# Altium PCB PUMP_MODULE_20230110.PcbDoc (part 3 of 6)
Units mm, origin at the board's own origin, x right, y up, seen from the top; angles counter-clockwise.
Board outline 260.15 x 142.01 mm, 4 copper layers (Top Layer, Mid-Layer 1, Mid-Layer 2, Bottom Layer); 422 components, 240 nets, 1746 pads, 416 vias.
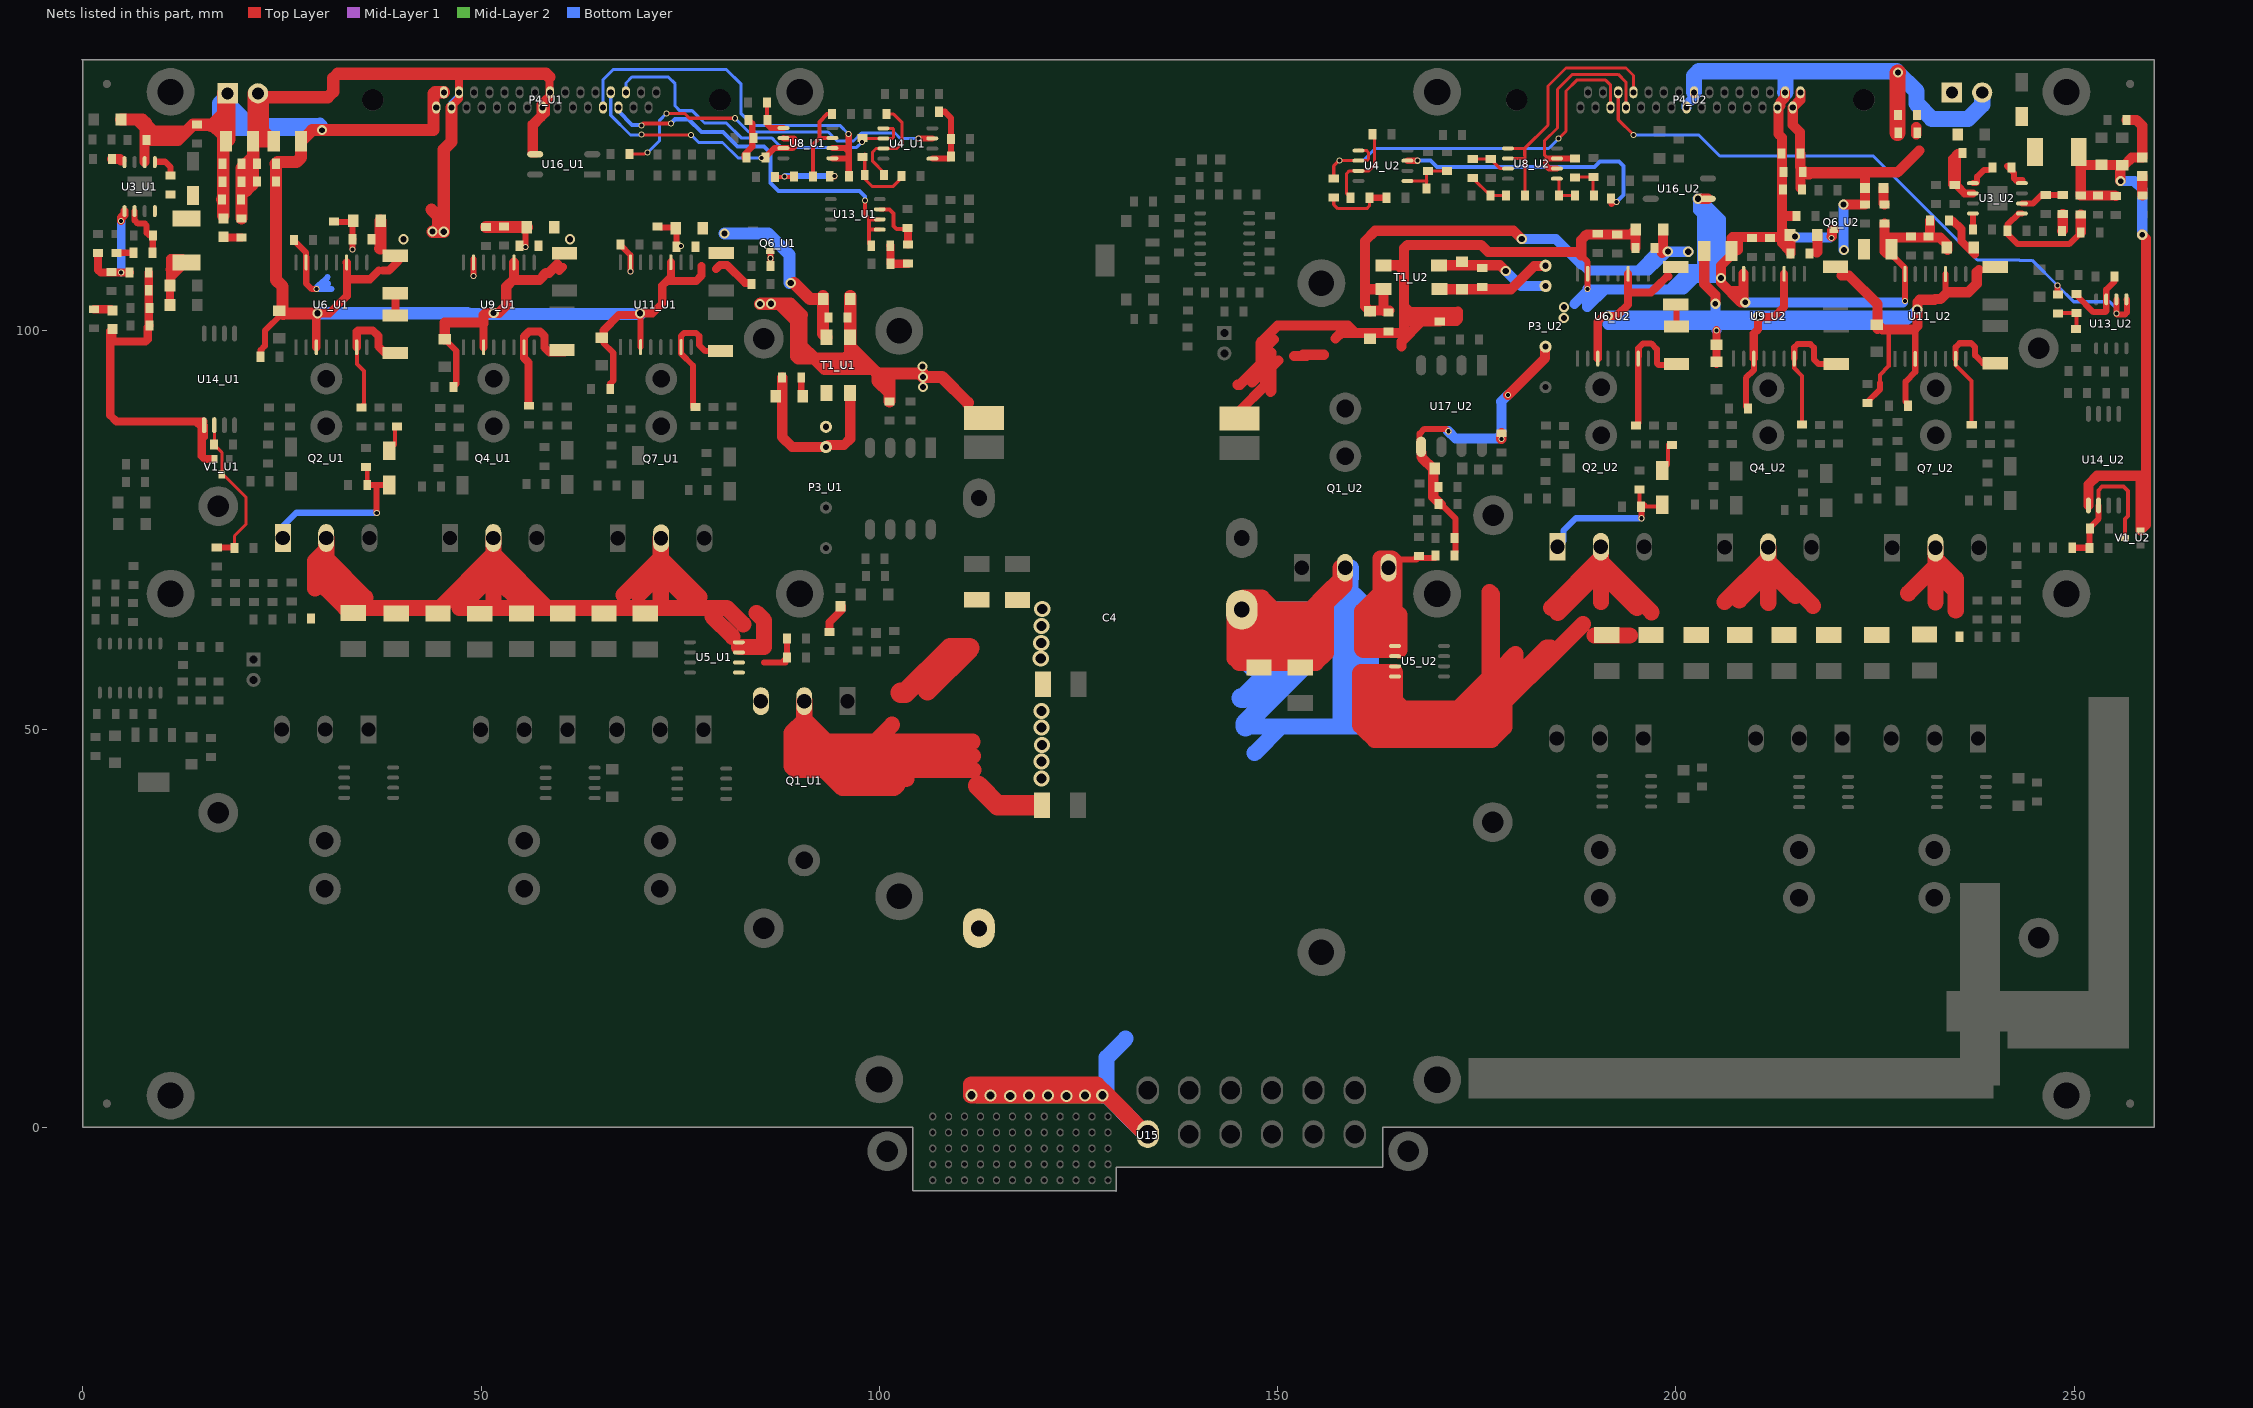
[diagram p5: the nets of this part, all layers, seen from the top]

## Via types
v1: diameter 0.762, hole 0.508, Top Layer to Bottom Layer, 208 vias
v2: diameter 2.032, hole 1.27, Top Layer to Bottom Layer, 78 vias
v3: diameter 1.27, hole 0.762, Top Layer to Bottom Layer, 61 vias
v4: diameter 1.524, hole 1.016, Top Layer to Bottom Layer, 53 vias
v5: diameter 1.27, hole 0.711, Top Layer to Bottom Layer, 16 vias

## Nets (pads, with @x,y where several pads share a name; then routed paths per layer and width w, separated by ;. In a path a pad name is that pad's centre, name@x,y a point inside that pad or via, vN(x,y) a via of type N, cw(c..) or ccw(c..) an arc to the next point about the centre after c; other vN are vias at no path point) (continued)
GND_HVISO_U2: C38_U2.2 C39_U2.2 C40_U2.2 P3_U2.3 R18_U2.2 R34_U2.2 R46_U2.1 U17_U2.5 | length 41.8
  Top Layer w0.762: U17_U2.5@167.818,84.963 167.818,87.097 168.427,87.706 171.12,87.706 v1(171.425,87.401) ; C39_U2.2@170.51,78.181 170.586,78.181 172.339,76.429 R18_U2.2@172.339,72.252
  Top Layer w1.27: U17_U2.5@168.046,84.734 168.046,84.15 169.647,82.55 169.545,82.448 169.545,79.146 C39_U2.2@170.51,78.181 ; v1(178.105,86.436) 178.079,86.462 178.079,86.614 178.105,86.639 R34_U2.2@178.105,87.147 ; v1(178.943,91.948) 183.591,96.596 P3_U2.3@183.591,97.993
  Bottom Layer w1.27: v1(171.425,87.401) 172.339,86.487 177.546,86.487 178.105,87.046 178.105,91.059 178.054,91.11 178.892,91.948 v1(178.943,91.948)
HVCC_IN: C4.1 C17.2 C18.2 C73.2 C74.2 C75.2 C76.2 Q1_U1.2 Q1_U2.2 U15.7 | length 548.8
  Top Layer w2.032: Q1_U1.2@90.572,53.619 Q1_U1.2@90.572,53.518 90.572,51.236 ; 101.6,50.546 99.466,48.412 ; 102.286,43.028 101.854,42.596 95.377,42.596 94.234,43.739 ; 103.378,43.739 94.234,43.739 ; 111.684,48.412 99.466,48.412 ; 111.735,46.634 91.948,46.634 ; 111.785,44.856 93.167,44.856 ; 112.37,4.039 v4(111.557,4.039) v4@111.531,4.013 ; v4@116.713,4.039 119.736,4.039 ; v4@118.745,4.394 118.77,4.394 119.024,4.14 119.837,4.14 ; 121.641,5.41 121.666,5.385 ; v4@123.749,4.039 119.736,4.039 ; 126.797,4.039 v4(127.991,4.039) v4@128.566,4.039 ; v4@128.422,4.14 v4@127.991,4.14 ; U15.7@133.741,-0.837 U15.7@133.7,-0.837 U15.7@133.527,-0.837 ; Q1_U2.2@157.916,70.256 157.916,68.838 156.058,66.98 ; Q1_U2.2@158.475,70.256 158.394,70.176 158.394,68.072 156.058,65.735 ; 88.976,46.812 88.976,49.53 90.572,51.126 ; 88.976,46.812 88.976,45.339 89.459,44.856 90.932,44.856 ; 88.976,46.812 90.932,44.856 ; 90.572,47.68 90.572,47.452 91.948,46.076 ; 90.572,47.68 91.618,46.634 91.948,46.634 ; 90.572,47.68 90.572,49.788 ; 90.572,49.788 90.572,51.126 ; 90.572,49.788 91.948,48.412 ; 90.572,51.126 90.572,51.236 ; 90.572,51.236 93.396,48.412 ; 90.932,44.856 93.116,44.856 ; 91.948,46.076 93.167,44.856 ; 91.948,46.076 91.948,46.634 ; 91.948,46.076 91.948,46.025 93.116,44.856 ; 91.948,46.634 91.948,48.412 ; 91.948,48.412 93.396,48.412 ; 93.116,44.856 94.234,43.739 ; 93.116,44.856 93.167,44.856 ; 93.396,48.412 99.466,48.412 ; v4@111.531,4.013 v4(113.944,4.013) v4(125.806,4.013) 126.619,4.013 v4@126.492,4.14 ; v4@111.531,4.013 111.531,5.385 121.666,5.385 ; 119.736,4.039 119.837,4.14 ; 119.837,4.14 v4@122.911,4.14 ; 121.666,5.385 126.746,5.385 ; 121.666,5.385 v4@122.911,4.14 ; v4@122.911,4.14 v4@126.492,4.14 ; v4@126.492,4.14 v4@127.991,4.14 ; 126.746,5.385 v4@127.991,4.14 ; 126.746,5.385 127.305,5.385 v4@128.651,4.039 ; v4@128.566,4.039 v4@128.651,4.039 ; v4@128.566,4.039 133.442,-0.837 U15.7@133.527,-0.837 ; v4@128.651,4.039 U15.7@133.527,-0.837 ; 144.628,60.96 144.628,58.877 145.186,58.318 154.813,58.318 156.058,59.563 156.058,61.087 ; 144.628,60.96 144.628,64.128 C4.1@145.5,65 ; 144.628,60.96 146.075,59.512 154.28,59.512 154.381,59.411 156.058,61.087 ; C4.1@145.5,63.771 C4.1@145.5,65 ; C4.1@145.5,63.771 145.5,62.399 146.355,61.544 154.635,61.544 156.058,62.967 ; C4.1@145.5,63.771 145.847,63.424 154.864,63.424 156.058,64.618 ; C4.1@145.5,65 149.53,65 ; C4.1@145.5,65 145.5,66.328 145.694,66.523 148.007,66.523 149.53,65 ; 149.53,65 154.078,65 156.058,66.98 ; 156.058,61.087 156.058,62.967 ; 156.058,62.967 156.058,64.618 ; 156.058,64.618 156.058,65.735 ; 156.058,65.735 156.058,66.98
  Top Layer w2.54: 102.692,54.534 102.667,54.559 103.276,54.559 108.89,60.173 111.328,60.173 106.045,54.889 ; 112.395,42.901 114.833,40.462 C76.2@119.913,40.462
  Mid-Layer 1 w2.032: v4@121.717,4.166 121.742,4.14 128.464,4.14 130.461,2.143 130.461,2.127 133.425,-0.837 U15.7@133.7,-0.837 U15.7@133.741,-0.837
  Mid-Layer 2 w2.032: v4@111.76,4.699 125.628,4.699 126.187,4.14 v4@127.94,4.14 ; v4@111.912,4.496 112.37,4.039 v4(127.991,4.039) 128.566,4.039 130.461,2.143 130.461,2.101 133.4,-0.837 U15.7@133.7,-0.837 U15.7@133.741,-0.837 ; 112.09,5.334 126.746,5.334 v4@127.94,4.14 ; v4@128.422,4.14 v4@127.94,4.14
  Bottom Layer w2.032: v4(127.991,4.039) v4@128.525,4.039 ; 130.912,11.151 128.525,8.764 v4@128.525,4.039 ; U15.7@133.7,-0.837 133.4,-0.837 v4@128.525,4.039 ; 145.974,50.343 150.47,50.343 ; 147.117,46.99 150.47,50.343 ; 147.701,61.468 153.34,61.468 154.991,61.468 157.916,64.393 ; 147.777,59.817 147.777,59.842 151.714,59.842 155.092,59.842 155.575,59.842 157.916,62.184 ; 158.043,68.449 Q1_U2.2@158.043,70.256 ; Q1_U2.2@159.182,70.256 159.182,68.991 159.156,69.016 159.156,67.335 159.842,66.65 ; 150.47,50.343 157.302,50.343 ; 157.302,50.343 158.75,50.343 ; 157.302,50.343 157.916,50.957 157.916,62.184 ; 157.916,62.184 157.916,64.393 ; 157.916,64.393 157.916,66.984 ; 157.916,66.984 157.916,68.102 154.814,65 C4.1@145.5,65 147.203,63.297 154.229,63.297 157.916,66.984 ; 158.75,50.343 161.138,50.343 161.722,50.927 161.722,64.77 159.842,66.65 ; 158.75,50.343 159.842,51.435 159.842,66.65
  Bottom Layer w2.54: 145.466,53.899 145.771,53.899 149.835,57.963 ; 145.974,50.343 145.974,50.724 155.092,59.842 ; 146.812,57.963 149.835,57.963 ; 153.34,61.468 151.714,59.842 149.835,57.963
  other v2: 120.345,43.815 120.345,45.923 120.421,48.006 120.371,50.19 120.371,52.299 120.269,58.852 120.32,60.808 120.345,62.967 120.447,65.1
  other v4: 116.434,3.962 123.495,3.962 118.796,3.988 121.158,3.988
HVCC_U1: C15_U1.2 C16_U1.2 C20_U1.2 C70_U1.2 C71_U1.2 C72_U1.2 C77_U1.2 C78_U1.2 Q2_U1.2 Q4_U1.2 Q7_U1.2 R74_U1.2 U5_U1.3 U5_U1.4 | length 159.1
  Top Layer w2.032: Q2_U1.2@30.56,74 Q2_U1.2@30.56,72.517 ; 33.604,66.497 30.56,69.541 ; 35.484,66.497 30.56,71.421 ; Q4_U1.2@51.56,74 51.56,71.935 ; 67.894,66.853 72.56,71.519 ; 69.774,66.878 72.56,69.664 ; Q7_U1.2@72.56,74 72.56,71.519 ; 76.048,66.269 72.56,69.756 ; 77.419,66.573 72.56,71.433 ; 79.045,64.135 81.585,61.595 ; 82.423,60.3 85.522,60.3 85.522,63.652 84.582,64.592 ; 82.906,63.17 80.848,65.227 72.644,65.227 ; 30.56,69.041 30.56,69.541 ; 30.56,69.041 30.56,67.611 32.944,65.227 44.856,65.227 51.56,71.931 ; 30.56,69.041 29.159,67.64 29.159,71.116 Q2_U1.2@30.56,72.517 ; 30.56,69.541 30.56,71.421 ; 30.56,71.421 Q2_U1.2@30.56,72.517 ; 51.56,69.344 51.56,65.483 51.816,65.227 ; 51.56,69.344 C72_U1.2@55.677,65.227 ; 51.56,69.344 51.56,69.492 ; 51.56,69.492 51.56,71.931 ; 51.56,69.492 47.295,65.227 51.816,65.227 ; 51.56,71.931 51.56,71.935 ; 51.56,71.935 58.268,65.227 ; 51.816,65.227 C72_U1.2@55.677,65.227 ; C72_U1.2@55.677,65.227 58.268,65.227 ; 58.268,65.227 72.644,65.227 ; 72.56,69.664 72.56,69.756 ; 72.56,69.664 72.56,65.311 72.644,65.227 ; 72.56,69.756 72.56,71.433 ; 72.56,71.433 72.56,71.519
HVCC_U2: C15_U2.2 C16_U2.2 C20_U2.2 C70_U2.2 C71_U2.2 C72_U2.2 C77_U2.2 C78_U2.2 Q2_U2.2 Q4_U2.2 Q7_U2.2 R74_U2.2 U5_U2.3 U5_U2.4 | length 255.8
  Top Layer w2.032: 172.822,52.73 175.514,55.423 ; 174.142,52.73 175.514,54.102 175.514,55.423 ; 174.6,51.054 176.581,53.035 ; 176.047,52.553 165.76,52.553 164.744,53.569 U5_U2.4@164.744,56.617 164.744,57.15 163.271,57.15 ; 176.505,50.876 178.283,52.654 ; 183.248,58.102 188.341,63.195 ; 184.252,60.249 183.794,60.249 179.857,56.312 ; 184.353,65.253 Q2_U2.2@190.601,71.501 ; 184.506,59.411 178.46,53.365 178.46,50.241 176.886,48.666 174.295,48.666 ; 185.166,64.567 190.601,70.002 ; C16_U2.2@189.763,61.747 194.208,61.747 ; 190.601,65.964 190.601,69.723 ; Q2_U2.2@190.601,72.83 Q2_U2.2@190.601,71.501 ; 195.123,65.202 190.601,69.723 ; 196.952,64.668 190.601,71.019 ; 206.096,65.964 Q4_U2.2@211.601,71.47 ; 207.95,66.167 211.601,69.819 ; Q4_U2.2@211.601,72.83 Q4_U2.2@211.601,71.47 ; 211.633,65.862 211.601,65.894 211.601,69.819 ; 215.011,66.7 211.601,70.11 ; 217.221,65.481 Q4_U2.2@211.601,71.101 ; 229.184,67.031 229.159,67.056 232.601,70.499 ; 232.588,65.938 232.601,65.952 232.601,69.862 ; Q7_U2.2@232.601,72.83 Q7_U2.2@232.601,71.411 ; 235.052,67.412 232.601,69.862 ; 235.128,64.897 235.128,68.885 Q7_U2.2@232.601,71.411 ; 161.036,49.809 162.179,48.666 164.694,48.666 ; 161.036,49.809 163.551,49.809 ; 161.036,49.809 160.35,50.495 160.35,57.023 160.477,57.15 161.747,57.15 ; 161.747,57.15 161.417,56.82 161.417,51.943 163.551,49.809 ; 161.747,57.15 163.271,57.15 ; 163.271,57.15 163.271,52.248 164.871,50.648 176.276,50.648 174.295,48.666 ; 163.551,49.809 164.694,48.666 ; 164.694,48.666 174.295,48.666 ; 175.514,55.423 176.581,56.49 ; 176.581,53.035 176.581,56.49 ; 176.581,53.035 178.079,54.534 ; 176.581,56.49 176.911,56.82 176.911,66.904 176.581,67.234 176.581,56.49 ; 178.079,54.534 179.857,56.312 ; 178.079,54.534 178.079,57.658 179.857,59.436 179.857,56.312 ; 190.601,69.723 190.601,70.002 ; 190.601,70.002 190.601,71.019 ; 190.601,71.019 Q2_U2.2@190.601,71.501 ; 211.601,69.819 211.601,70.11 ; 211.601,70.11 Q4_U2.2@211.601,71.101 ; Q4_U2.2@211.601,71.101 Q4_U2.2@211.601,71.47 ; 232.601,69.862 232.601,70.499 ; 232.601,70.499 Q7_U2.2@232.601,71.411
HVCCIN_U1: Q1_U1.3 R15_U1.1 R18_U1.1 U5_U1.1 U5_U1.2 | length 6
  Top Layer w0.762: 85.547,58.344 87.757,58.344 ; 88.189,58.344 87.757,58.344 ; R18_U1.1@88.417,61.392 R15_U1.1@88.417,59.004 87.757,58.344
HVCCIN_U2: Q1_U2.3 R15_U2.1 R18_U2.1 U5_U2.1 U5_U2.2 | length 66.2
  Top Layer w0.762: Q1_U2.3@163.356,70.256 164.423,71.323 R15_U2.1@167.411,71.323 ; R15_U2.1@167.361,71.526 167.386,71.501 R18_U2.1@169.774,71.501
  Top Layer w2.032: Q1_U2.3@163.297,69.901 163.297,67.462 162.916,67.081 ; Q1_U2.3@163.356,70.256 163.356,66.26 ; Q1_U2.3@163.483,70.256 Q1_U2.3@163.944,69.795 ; 161.722,59.969 160.757,59.969 160.63,60.096 160.63,64.795 162.916,67.081 ; 161.722,59.969 163.525,59.969 ; 161.722,59.969 161.671,60.02 161.671,64.592 163.347,66.269 ; 162.916,67.081 162.916,71.425 164.321,71.425 164.423,71.323 164.643,71.103 Q1_U2.3@164.643,69.097 ; 162.916,67.081 162.916,66.7 163.347,66.269 ; 163.347,66.269 163.347,60.147 163.525,59.969 ; 163.347,66.269 163.356,66.26 ; 163.356,66.26 163.944,65.672 ; 163.525,59.969 165.151,59.969 165.227,59.893 165.261,59.927 165.261,64.355 164.643,64.973 ; 163.944,65.672 164.643,64.973 ; 163.944,65.672 Q1_U2.3@163.944,69.795 ; Q1_U2.3@163.944,69.795 Q1_U2.3@164.643,69.097 ; 164.643,64.973 Q1_U2.3@164.643,69.097
II_1_AC1_U1: C45_U1.2 P4_U1.12 U8_U1.1 U8_U1.2 | length 50
  Top Layer w0.762: U8_U1.1@94.107,121.666 96.164,121.666 ; U8_U1.2@94.107,122.936 95.733,122.936 96.164,122.504 ; v1(96.139,124.714) 96.164,124.689 96.164,122.504 ; C45_U1.2@96.164,119.405 96.164,121.666 ; 96.164,121.666 96.164,122.504
  Bottom Layer w0.381: P4_U1.12@65.329,128.047 65.329,131.546 66.573,132.791 80.823,132.791 82.652,130.962 82.652,127.254 84.099,125.806 95.047,125.806 v1(96.139,124.714)
II_1_AC1_U2: C45_U2.2 P4_U2.12 U8_U2.1 U8_U2.2 | length 33.3
  Top Layer w0.381: U8_U2.2@178.918,121.641 181.026,121.641 ; U8_U2.1@178.918,122.911 181.026,122.911 ; C45_U2.2@181.077,116.992 181.077,121.996 181.026,122.047 181.026,122.911 ; P4_U2.12@194.668,129.952 194.668,132.052 193.726,132.994 186.207,132.994 183.947,130.734 183.947,125.832 181.026,122.911
II_1_AC2_U1: C48_U1.2 P4_U1.27 U8_U1.6 U8_U1.7 | length 31
  Top Layer w0.381: v1(70.155,124.663) 70.206,124.612 73.558,124.612 ; 73.584,124.587 73.558,124.612 ; v1@76.352,124.562 76.302,124.612 73.558,124.612
  Top Layer w0.762: C48_U1.2@85.471,121.691 85.573,121.691 86.817,122.936 U8_U1.7@87.96,122.936 89.103,122.936 89.332,123.165 89.332,124.054 89.306,124.079 89.306,124.155 88.011,124.155 U8_U1.6@87.96,124.206
  Bottom Layer w0.381: P4_U1.27@66.281,129.952 66.282,127.063 68.758,124.587 v1@70.155,124.587 ; v1(76.352,124.612) 77.318,123.647 80.315,123.647 82.271,121.691 v1(85.192,121.691)
II_1_AC2_U2: C48_U2.2 P4_U2.27 U8_U2.6 U8_U2.7 | length 28.4
  Top Layer w0.381: 183.972,121.641 183.947,121.641 183.49,122.098 183.49,123.825 185.141,125.476 185.141,130.327 187.02,132.207 192.761,132.207 193.716,131.252 P4_U2.27@193.716,128.047
  Top Layer w0.762: U8_U2.6@185.064,120.371 184.099,120.371 183.718,120.752 183.718,121.387 183.972,121.641 U8_U2.7@185.064,121.641 187.3,121.641 C48_U2.2@187.325,121.666
II_1_AC3_U1: C61_U1.2 P4_U1.13 U13_U1.1 U13_U1.2 | length 48.1
  Top Layer w0.508: v1(70.155,125.806) 70.383,126.035 73.838,126.035 v1(73.838,126.06) ; v1(98.222,116.357) 98.222,114.605 98.831,113.995 ; C61_U1.2@98.984,110.693 98.679,110.998 98.679,112.7 ; U13_U1.1@100.051,112.725 98.704,112.725 98.679,112.7 ; U13_U1.2@100.051,113.995 98.831,113.995 ; 98.679,112.7 98.679,113.843 98.831,113.995
  Bottom Layer w0.508: P4_U1.13@67.234,128.047 67.234,127.584 68.961,125.857 70.104,125.857 v1@70.206,125.755 ; v1@73.838,126.035 74.371,126.568 76.048,126.568 77.673,124.943 80.391,124.943 82.182,123.152 85.534,123.152 86.335,122.352 86.335,118.593 87.351,117.577 97.536,117.577 98.222,116.891 v1(98.222,116.357)
II_1_AC3_U2: C61_U2.2 P4_U2.13 U13_U2.1 U13_U2.2 | length 82.6
  Top Layer w0.381: P4_U2.13@192.763,129.952 192.763,126.515 v1(194.691,124.587) v1@194.615,124.663
  Top Layer w0.762: v1(247.904,105.689) 247.904,104.597 C61_U2.2@247.955,104.546 ; U13_U2.2@255.295,103.962 v1(255.295,102.184) 255.397,102.083 256.388,102.083 256.616,102.311 256.616,103.911 U13_U2.1@256.565,103.962
  Bottom Layer w0.381: v1(194.691,124.587) 202.87,124.587 205.511,121.945 ; 205.537,121.945 224.79,121.945 237.846,108.89 243.129,108.89 243.154,108.864 244.729,108.864 v1(247.904,105.689) 249.936,103.657 254.457,103.657 255.295,102.819 v1(255.295,102.184)
  Bottom Layer w0.762: v1@247.879,105.664 v1(247.904,105.689)
II_1_DC1_U1: C31_U1.2 P4_U1.28 U4_U1.1 U4_U1.2 | length 42.7
  Top Layer w0.381: C31_U1.2@98.222,124.155 U4_U1.2@100.508,124.155 101.625,124.155 101.778,124.308 101.778,125.349 101.702,125.425 U4_U1.1@100.508,125.425
  Bottom Layer w0.381: P4_U1.28@68.186,129.952 68.186,131.127 68.936,131.877 73.508,131.877 74.371,131.013 74.371,128.27 74.346,128.245 74.955,127.635 76.505,127.635 78.054,126.086 80.797,126.086 82.652,124.231 86.487,124.231 87.02,123.698 87.681,123.038 97.155,123.038 v1(97.815,123.698)
II_1_DC1_U2: C31_U2.2 P4_U2.28 U4_U2.1 U4_U2.2 | length 52.9
  Top Layer w0.381: C31_U2.2@157.048,119.126 157.048,120.726 157.683,121.361 U4_U2.2@160.147,121.361 160.172,121.387 161.239,121.387 161.417,121.564 161.417,122.403 161.188,122.631 U4_U2.1@160.147,122.631 U4_U2.1@160.223,122.707 ; v1(185.268,124.13) 186.207,125.07 186.207,125.832 ; 186.182,125.806 186.207,125.832 ; P4_U2.28@191.811,128.047 191.811,130.846 191.186,131.47 187.554,131.47 186.207,130.124 186.207,125.832
  Bottom Layer w0.381: v1(157.785,121.387) 160.757,121.387 162.255,122.885 184.023,122.885 v1(185.268,124.13)
II_FLT_U1: R86_U1.1 U4_U1.7 | length 43.6
  Top Layer w0.381: R86_U1.1@68.656,122.199 70.51,122.199 v1@70.752,122.441 ; v1(73.279,127.305) 75.54,127.305 76.149,126.695 v1(81.89,126.695)
  Top Layer w0.762: v1(104.902,124.155) U4_U1.7@106.655,124.155
  Bottom Layer w0.381: v1(70.891,122.377) 72.415,123.901 72.415,126.441 v1(73.279,127.305) ; v1(81.89,126.695) 83.617,124.968 93.574,124.968 94.691,123.85 96.749,123.85 97.739,124.841 101.168,124.841 101.956,124.841 102.641,124.155 v1(104.902,124.155)
II_FLT_U2: R86_U2.1 U4_U2.7 | length 33.6
  Top Layer w0.762: U4_U2.7@166.294,121.361 v1(167.538,121.361) ; 191.922,115.926 192.176,116.18 v1(192.557,116.18)
  Bottom Layer w0.508: v1(167.538,121.361) 169.215,121.361 170.002,120.574 189.763,120.574 190.449,121.26 192.862,121.26 193.421,120.701 193.421,117.043 v1(192.557,116.18)
ISO_+5V_U1: C21_U1.1 C22_U1.1 C23_U1.1 C29_U1.2 C30_U1.2 D3_U1.1 L1_U1.1 R20_U1.2 U14_U1.1 V1_U1.2 | length 56.4
  Top Layer w1.016: C23_U1.1@8.28,107.315 R20_U1.2@8.28,105.105 8.28,100.787 C30_U1.2@8.382,100.686 8.153,100.457 8.153,98.933 7.899,98.679 3.912,98.679 3.708,98.882 D3_U1.1@3.708,100.228 3.454,99.974 3.454,89.408 4.242,88.621 14.224,88.621 ; 10.922,107.721 10.947,107.696 ; C22_U1.1@10.947,103.251 C21_U1.1@10.947,105.715 10.947,106.68 ; U14_U1.1@15.164,88.621 14.224,88.621 ; U14_U1.1@15.189,88.113 15.189,86.665 14.935,86.411 ; V1_U1.2@16.281,83.896 15.342,83.896 14.935,84.303 14.935,86.411 ; 10.947,106.68 10.947,107.696 ; 10.947,106.68 11.074,106.68 L1_U1.1@13.005,108.61 12.497,109.118 10.998,109.118 10.947,109.068 10.947,107.696 ; 14.224,88.621 14.935,87.909 14.935,86.411
ISO_+5V_U2: C21_U2.1 C22_U2.1 C23_U2.1 C29_U2.2 C30_U2.2 D3_U2.1 L1_U2.1 R20_U2.2 U14_U2.1 V1_U2.2 | length 94
  Top Layer w0.508: 253.34,81.509 257.785,81.509
  Top Layer w1.27: L1_U2.1@250.571,122.479 250.571,121.361 L1_U2.1@250.825,121.107 ; U14_U2.1@251.79,78.08 251.79,80.721 252.882,81.813 258.318,81.813 V1_U2.2@258.318,74.955 259.007,75.644 259.007,111.605 v5(258.547,112.065) ; C29_U2.2@255.219,116.942 255.143,117.018 C23_U2.1@250.825,117.018 L1_U2.1@250.825,121.107 ; v5(255.829,118.796) 255.778,118.847 255.778,120.548 C22_U2.1@256.032,120.802 ; C30_U2.2@256.565,126.492 257.81,126.492 258.547,125.755 D3_U2.1@258.547,121.742 257.226,121.742 256.311,120.828 C21_U2.1@253.416,120.828 251.104,120.828 L1_U2.1@250.825,121.107
  Bottom Layer w1.27: v5(255.829,118.796) 257.556,118.796 258.547,117.805 v5(258.547,112.065)
ISO_+15V_U1: C5_U1.1 C6_U1.1 C7_U1.2 C8_U1.2 C9_U1.2 C10_U1.2 C11_U1.2 C19_U1.1 C24_U1.1 C25_U1.2 C34_U1.1 C35_U1.1 C41_U1.1 C42_U1.1 C43_U1.1 C44_U1.1 C49_U1.1 C50_U1.1 C51_U1.1 C52_U1.1 C66_U1.1 C67_U1.1 C68_U1.1 D1_U1.1 D6_U1.1 D11_U1.1 D16_U1.1 P2_U1.1 P4_U1.1 P4_U1.16 R17_U1.1 R51_U1.2 T1_U1.2 U3_U1.2 U6_U1.3 U6_U1.11 U9_U1.3 U9_U1.11 U11_U1.3 U11_U1.11 | length 314.3
  Top Layer w0.762: C68_U1.1@22.327,96.749 22.327,97.587 22.86,98.12 22.86,100.025 25.019,102.184 C43_U1.1@25.095,102.184 ; C51_U1.1@45.441,98.933 46.888,97.485 46.888,93.32 C44_U1.1@46.533,92.964 ; C19_U1.1@65.354,99.162 65.354,98.476 66.599,97.231 66.599,93.751 66.218,93.37 C52_U1.1@66.218,92.71 ; v3@70.002,101.981 70.002,102.006 70.028,101.981 U11_U1.3@70.028,97.968
  Top Layer w1.016: 24.181,106.324 24.257,106.401 ; U6_U1.3@29.312,97.942 29.312,102.057 29.439,102.184 v3(29.464,102.21) 30.988,102.21 33.147,104.369 33.147,108.567 U6_U1.11@33.122,108.592 ; 33.241,106.477 36.068,106.477 37.16,107.569 ; 37.668,107.594 38.456,107.594 D6_U1.1@39.624,108.763 ; U9_U1.3@50.317,97.942 50.317,100.94 ; 59.817,107.518 60.3,108.001 ; C19_U1.1@65.227,98.882 C19_U1.1@65.253,98.908 ; C19_U1.1@65.354,99.162 65.354,100.051 67.285,101.981 70.002,101.981 v3@70.028,101.981 ; v3(69.952,102.21) 71.526,102.21 72.746,103.429 72.746,105.689 73.33,106.274 ; U11_U1.11@73.838,108.618 73.838,106.782 73.33,106.274 ; 77.673,108.128 77.673,106.934 77.013,106.274 73.33,106.274 ; 79.502,107.772 80.01,108.28 80.874,108.28 83.16,105.994 R51_U1.2@83.541,105.994
  Top Layer w1.27: 6.68,126.517 7.772,125.425 U3_U1.2@7.772,121.183 ; C51_U1.1@45.441,98.933 45.441,101.016 45.491,101.067 50.19,101.067 50.317,100.94 50.317,101.956 50.597,102.235 v3(51.587,102.235) 52.222,102.235 53.162,103.175 53.162,105.537 54.127,106.502 U9_U1.11@54.127,108.592 ; 54.407,106.375 57.328,106.375 57.785,106.832 57.785,106.909 58.166,107.29 58.522,107.29 59.563,108.331
  Top Layer w1.524: C24_U1.1@4.801,126.517 6.68,126.517 7.518,126.517 8.001,126.035 8.001,125.882 8.839,125.044 ; 8.001,125.73 8.001,125.298 ; 16.078,125.73 16.231,125.882 ; C10_U1.2@17.501,116.484 C10_U1.2@17.628,116.611 ; D1_U1.1@17.628,114.452 C10_U1.2@17.628,116.611 ; P2_U1.1@17.628,129.845 17.628,127.279 ; C43_U1.1@25.07,102.641 25.07,105.588 24.257,106.401 C8_U1.2@24.257,118.77 24.257,120.955 C9_U1.2@24.232,120.98 24.46,121.209 26.848,121.209 27.407,121.768 C5_U1.1@27.407,123.8 28.804,125.197 v5(30.023,125.197) 44.044,125.197 44.044,129.794 44.202,129.952 P4_U1.16@45.326,129.952 ; C43_U1.1@25.095,102.184 C43_U1.1@25.171,102.108 ; C43_U1.1@25.375,102.184 v3@29.439,102.184 ; 37.338,110.363 37.389,110.414 C49_U1.1@37.389,113.817 ; v3@89.281,106.02 91.288,104.013 C34_U1.1@92.913,104.013 ; C34_U1.1@92.913,104.394 C34_U1.1@92.913,104.013 ; C34_U1.1@92.939,104.013 C34_U1.1@92.913,104.013 ; T1_U1.2@93.345,99.202 92.913,99.634 C34_U1.1@92.913,104.013 ; 8.001,125.298 R17_U1.1@8.001,123.977 9.855,123.977 ; 8.001,125.298 8.255,125.044 8.839,125.044 ; 8.839,125.044 9.881,124.003 9.855,123.977 ; 8.839,125.044 13.005,125.044 ; 9.855,123.977 11.938,123.977 13.005,125.044 ; 13.005,125.044 13.843,125.882 C25_U1.2@14.351,125.882 16.231,125.882 ; 16.231,125.882 C6_U1.1@17.628,124.485 ; 16.231,125.882 17.628,125.882 ; 16.231,125.882 17.628,127.279 ; C10_U1.2@17.628,116.611 C6_U1.1@17.628,124.485 ; C6_U1.1@17.628,124.485 17.628,125.882 ; C6_U1.1@17.628,124.485 17.958,124.155 C6_U1.1@17.958,123.8 18.212,123.8 18.44,124.028 18.44,129.565 P2_U1.1@18.186,129.819 18.186,127.838 17.628,127.279 ; 17.628,125.882 17.628,127.279
  Bottom Layer w1.524: 21.895,125.197 21.869,125.197 ; v3@29.743,102.21 48.285,102.21 48.362,102.133 v3@70.002,102.133 ; v3(80.569,112.217) 86.055,112.217 88.722,109.55 v3@88.722,106.045 ; 18.186,125.908 16.967,127.127 16.967,128.6 P2_U1.1@18.186,129.819 P2_U1.1@18.186,128.88 ; 18.186,125.908 18.186,127.686 ; 18.186,125.908 18.898,125.197 21.869,125.197 ; 18.186,127.686 P2_U1.1@18.186,128.88 ; 18.186,127.686 19.888,125.984 21.082,125.984 ; P2_U1.1@18.186,128.88 21.082,125.984 ; 21.082,125.984 29.743,125.984 29.769,126.009 30.023,125.755 v5(30.023,125.197) 21.869,125.197 ; 21.082,125.984 21.869,125.197
  other v3: 88.875,105.994 40.284,111.506 61.189,111.506
ISO_+15V_U2: C5_U2.1 C6_U2.1 C7_U2.2 C8_U2.2 C9_U2.2 C10_U2.2 C11_U2.2 C19_U2.1 C24_U2.1 C25_U2.2 C34_U2.1 C35_U2.1 C41_U2.1 C42_U2.1 C43_U2.1 C44_U2.1 C49_U2.1 C50_U2.1 C51_U2.1 C52_U2.1 C66_U2.1 C67_U2.1 C68_U2.1 D1_U2.1 D6_U2.1 D11_U2.1 D16_U2.1 P2_U2.1 P4_U2.1 P4_U2.16 R17_U2.1 R51_U2.2 T1_U2.2 U3_U2.2 U6_U2.3 U6_U2.11 U9_U2.3 U9_U2.11 U11_U2.3 U11_U2.11 | length 325.2
  Top Layer w0.508: 225.628,93.421 225.628,94.488 226.72,95.58 226.72,100.051 226.822,100.152
  Top Layer w0.762: C43_U2.1@205.08,96.672 C43_U2.1@205.207,96.545 ; C44_U2.1@209.067,90.246 208.788,90.526 208.788,94.093 209.779,95.083 U9_U2.3@209.779,96.469 ; U9_U2.3@209.702,96.545 U9_U2.3@209.779,96.469 ; U9_U2.3@209.779,96.52 U9_U2.3@209.779,96.469 ; C68_U2.1@224.053,90.932 224.053,91.097 225.628,92.672 225.628,93.421 ; C52_U2.1@229.032,90.907 228.829,91.11 228.829,93.624 230.048,94.844 U11_U2.3@230.048,96.495 230.048,99.974 229.87,100.152 ; U11_U2.11@233.858,107.145 233.858,105.08 234.086,104.851
  Top Layer w1.016: U6_U2.3@190.195,96.52 190.195,101.143 190.906,101.854 v3(191.44,101.854) 192.557,101.854 193.319,102.616 193.345,102.616 194.005,103.276 194.005,104.8 ; U6_U2.11@194.005,107.17 194.005,104.8 ; 199.06,106.858 198.907,106.858 197.561,105.512 196.85,104.8 194.005,104.8 ; C43_U2.1@205.08,95.834 205.08,96.672 C51_U2.1@205.08,98.273 v1(205.08,100.076) ; U9_U2.3@209.779,96.52 209.779,99.67 210.287,100.178 210.287,101.295 210.744,101.752 212.344,101.752 213.589,102.997 U9_U2.11@213.589,107.17 ; C50_U2.1@234.29,113.868 234.747,113.868 235.839,112.776 235.839,111.252 237.515,109.576 ; R17_U2.1@235.331,118.186 236.245,117.272 U3_U2.2@237.287,117.272 ; 235.356,122.326 235.28,122.25 ; 235.28,122.25 235.28,118.618 R17_U2.1@235.001,118.339 234.721,118.339 234.696,118.364 234.696,121.666 235.28,122.25
  Top Layer w1.27: C35_U2.1@164.008,102.54 C35_U2.1@163.307,102.54 ; v3(180.645,111.531) 179.603,112.573 162.255,112.573 160.96,111.277 160.96,105.689 ; 198.247,109.753 198.399,109.906 C41_U2.1@198.399,112.725 ; C6_U2.1@203.556,109.449 203.556,105.893 204.953,104.496 v5@204.953,103.632 ; C8_U2.2@215.621,117.958 C11_U2.2@215.621,120.523 ; C7_U2.2@215.621,122.276 C11_U2.2@215.621,120.523 ; P4_U2.1@215.623,129.952 215.623,128.999 P4_U2.16@214.671,128.047 214.671,125.841 215.57,124.943 215.57,120.574 C11_U2.2@215.621,120.523 ; 217.678,109.855 217.754,109.931 C66_U2.1@217.754,112.039 ; 220.802,106.934 221.742,106.934 225.323,103.353 C19_U2.1@225.323,100.787 ; v3@221.056,115.875 221.082,115.849 R51_U2.2@223.749,115.849 D1_U2.1@223.749,117.958 223.749,119.761 ; C19_U2.1@225.323,100.228 C19_U2.1@225.323,100.787 ; C10_U2.2@230.175,124.638 230.175,125.603 ; 230.556,122.631 227.838,119.913 223.901,119.913 ; 238.049,107.645 237.769,107.366 237.769,105.918 236.703,104.851 234.086,104.851 233.223,103.988 232.512,103.988 232.435,103.911 230.607,103.911 230.327,103.632 230.327,100.609 229.87,100.152 226.822,100.152 225.958,100.152 C19_U2.1@225.323,100.787 ; 160.96,105.689 160.96,103.099 C34_U2.1@161.62,102.438 161.722,102.54 163.246,102.54 ; 160.96,105.689 161.417,105.232 T1_U2.2@163.307,105.232 C35_U2.1@163.307,102.54 ; 163.246,102.54 C35_U2.1@163.307,102.54 ; 163.246,102.54 163.307,102.479 C35_U2.1@163.307,102.54 ; C11_U2.2@215.621,120.523 C11_U2.2@216.23,119.913 ; C11_U2.2@216.23,119.913 216.51,119.634 216.789,119.634 216.916,119.761 223.749,119.761 ; C11_U2.2@216.23,119.913 223.901,119.913 ; 223.749,119.761 223.901,119.913
  Bottom Layer w1.27: v3(180.645,111.531) 184.912,111.531 188.087,108.356 ; 188.087,108.509 189.027,107.569 195.25,107.569 ; 198.069,109.245 197.574,108.75 ; v3@198.984,109.931 v3(201.549,109.931) ; v5@204.953,103.251 204.953,101.905 ; v1(205.08,100.076) 205.08,100.762 ; v3@221.031,110.16 v3(221.031,115.875) ; v3(230.302,102.667) 229.54,101.905 ; 195.25,107.569 196.393,107.569 ; 195.25,107.569 197.663,109.982 v3(198.984,109.982) 197.752,108.75 ; 196.393,107.569 196.571,107.569 197.752,108.75 ; 196.393,107.569 197.574,108.75 ; 197.574,108.75 197.752,108.75 ; 204.953,101.905 229.54,101.905 ; 204.953,101.905 191.491,101.905 v3(191.44,101.854) 191.44,100.787 191.465,100.762 205.08,100.762 ; 204.953,101.905 205.08,101.778 205.08,100.762 ; 205.08,100.762 228.397,100.762 229.54,101.905
  other v3: 210.337,101.854 221.107,110.16
  other v5: 204.953,103.403
ISO_GND_U1: C5_U1.2 C6_U1.2 C7_U1.1 C8_U1.1 C9_U1.1 C10_U1.1 C11_U1.1 C34_U1.2 C35_U1.2 C41_U1.2 C42_U1.2 C49_U1.2 C50_U1.2 C66_U1.2 C67_U1.2 P2_U1.2 P4_U1.2 P4_U1.8 P4_U1.17 P4_U1.23 Q6_U1.2 R8_U1.1 R21_U1.1 R31_U1.2 R33_U1.2 R45_U1.1 R48_U1.2 R50_U1.2 R58_U1.1 R63_U1.2 R65_U1.2 T1_U1.4 U6_U1.15 U9_U1.15 U11_U1.15 U16_U1.4 | length 243.9
  Top Layer w0.762: R33_U1.2@26.543,111.404 26.543,111.303 28.042,109.804 U6_U1.15@28.042,108.592 28.042,105.943 28.067,105.918 ; U6_U1.15@28.067,109.296 28.067,105.918 ; v1(29.337,105.232) 28.753,105.232 28.067,105.918 ; R31_U1.2@31.775,113.665 C49_U1.2@33.731,113.665 ; v1(33.884,110.236) C67_U1.2@33.884,111.404 ; C49_U1.2@33.884,113.64 C67_U1.2@33.884,111.404 ; C49_U1.2@33.96,113.817 C49_U1.2@34.138,113.64 ; C67_U1.2@33.985,111.506 C67_U1.2@33.884,111.404 ; v1(49.047,106.883) U9_U1.15@49.047,109.009 ; R48_U1.2@52.857,113.081 C66_U1.2@55.27,113.081 ; C50_U1.2@54.839,110.693 55.448,110.693 v1(55.601,110.541) 55.601,112.852 C66_U1.2@55.753,113.005 ; P4_U1.23@58.661,129.952 P4_U1.23@58.661,129.781 ; R65_U1.2@67.513,110.846 67.513,110.744 68.758,109.499 U11_U1.15@68.758,108.618 v1(68.758,107.442) ; R63_U1.2@72.593,112.954 C41_U1.2@74.371,112.954 ; C42_U1.2@74.524,110.922 74.524,112.065 ; Q6_U1.2@86.309,109.83 86.36,109.779 v1(86.36,109.118) R58_U1.1@86.36,108.001 ; 57.328,127.102 57.328,128.448 57.709,128.829 ; 57.328,127.102 P4_U1.8@57.709,127.483 ; 57.328,127.102 56.236,126.009 56.236,122.25 56.363,122.123 56.972,122.123 56.744,122.352 56.744,125.705 57.709,126.67 ; 57.709,126.67 58.268,127.229 58.268,128.676 ; 57.709,126.67 P4_U1.8@57.709,127.483 ; P4_U1.8@57.709,127.483 P4_U1.8@57.709,128.047 P4_U1.8@57.709,128.118 ; P4_U1.8@57.709,128.118 58.268,128.676 ; P4_U1.8@57.709,128.118 57.709,128.829 ; 57.709,128.829 P4_U1.23@58.661,129.781 ; 58.268,128.676 58.661,129.07 P4_U1.23@58.661,129.781
  Top Layer w1.016: P4_U1.2@46.279,128.047 46.279,128.192 47.231,129.144 P4_U1.17@47.231,129.952 47.231,132.143 47.371,132.283 ; 58.572,131.851 58.572,129.87 P4_U1.23@58.661,129.781
  Top Layer w1.524: R8_U1.1@19.939,114.097 19.914,114.122 19.914,117.577 ; C9_U1.1@21.438,120.675 21.438,121.971 ; 43.764,115.24 44.577,114.427 ; v3(43.891,112.471) 43.917,112.446 v3@45.085,112.446 ; P4_U1.2@46.279,128.047 46.279,123.749 45.314,122.784 v3(45.314,112.446) v3@45.085,112.446 ; R50_U1.2@50.622,113.03 55.728,113.03 C66_U1.2@55.753,113.005 ; 58.572,131.851 58.141,132.283 47.371,132.283 32.004,132.283 31.445,131.724 31.445,130.023 30.759,129.337 P2_U1.2@21.946,129.337 ; v3(85.039,103.378) 85.065,103.403 v3(86.385,103.403) 87.401,103.403 ; C34_U1.2@96.342,104.394 96.345,104.391 T1_U1.4@96.345,99.202 96.345,98.067 ; 100.889,94.336 101.295,93.929 101.295,92.177 ; R45_U1.1@101.295,91.161 101.295,92.177 ; v3@105.385,94.691 105.334,94.64 99.771,94.64 ; v3(105.461,94.209) 107.874,94.209 111.1,90.983 ; 19.914,117.577 20.523,117.577 21.285,118.339 ; 19.914,117.577 C11_U1.1@19.914,118.72 ; C11_U1.1@19.914,118.72 19.914,120.447 21.387,121.92 ; C11_U1.1@19.914,118.72 20.904,118.72 21.285,118.339 ; 21.285,118.339 21.387,118.44 21.387,121.92 ; 21.387,121.92 C6_U1.2@21.387,123.8 ; 21.387,121.92 21.438,121.971 ; C6_U1.2@21.387,123.8 C6_U1.2@21.438,123.8 ; C6_U1.2@21.387,123.8 C6_U1.2@21.438,123.85 ; 21.438,121.971 C6_U1.2@21.438,123.8 ; C6_U1.2@21.438,123.8 C6_U1.2@21.438,123.85 ; C6_U1.2@21.438,123.8 C5_U1.2@23.978,123.8 22.987,124.79 22.682,124.79 22.606,124.866 22.606,128.676 P2_U1.2@21.946,129.337 ; C6_U1.2@21.438,123.85 21.438,129.845 P2_U1.2@21.946,129.337 ; 44.577,112.471 45.06,112.471 v3@45.085,112.446 ; 44.577,112.471 44.577,114.427 ; 44.577,112.471 v3@45.085,112.979 ; 44.577,114.427 45.085,113.919 v3@45.085,112.979 ; v3@45.085,112.446 v3@45.085,112.979 ; 87.401,103.403 88.849,103.403 90.272,101.981 ; 87.401,103.403 88.824,101.981 ; 88.824,101.981 89.56,101.244 ; 88.824,101.981 90.272,101.981 ; 89.56,101.244 90.246,100.559 ; 89.56,101.244 89.56,96.774 89.814,96.52 91.846,96.52 ; 90.246,100.559 90.246,98.12 91.846,96.52 ; 90.246,100.559 90.246,101.956 90.272,101.981 ; 91.846,96.52 93.116,95.25 99.162,95.25 ; 91.846,96.52 95.733,96.52 ; 95.733,96.52 97.663,96.52 97.777,96.634 ; 95.733,96.52 96.345,97.132 96.345,98.067 ; 96.345,98.067 97.777,96.634 ; 97.777,96.634 99.162,95.25 ; 99.162,95.25 99.771,94.64 ; 99.771,94.64 99.771,93.701 101.295,92.177
  Bottom Layer w0.762: v1(29.337,105.232) 30.099,105.232 30.15,105.283 31.217,105.283 ; 30.734,106.756 29.82,105.842 ; 30.759,105.918 30.683,105.842 29.82,105.842 ; 29.82,105.842 29.477,105.499 29.4,105.499 29.743,105.842 29.82,105.842
  Bottom Layer w1.016: P4_U1.2@46.279,128.047 46.279,128.423 47.231,129.375 P4_U1.17@47.231,129.952
  other v1: 75.108,110.668
  other v3: 105.461,92.964 105.435,95.529
ISO_GND_U2: C5_U2.2 C6_U2.2 C7_U2.1 C8_U2.1 C9_U2.1 C10_U2.1 C11_U2.1 C34_U2.2 C35_U2.2 C41_U2.2 C42_U2.2 C49_U2.2 C50_U2.2 C66_U2.2 C67_U2.2 P2_U2.2 P4_U2.2 P4_U2.8 P4_U2.17 P4_U2.23 Q6_U2.2 R8_U2.1 R21_U2.1 R31_U2.2 R33_U2.2 R45_U2.1 R48_U2.2 R50_U2.2 R58_U2.1 R63_U2.2 R65_U2.2 T1_U2.4 U6_U2.15 U9_U2.15 U11_U2.15 U16_U2.4 | length 348.5
  Top Layer w0.762: 187.681,109.906 188.112,109.474 188.925,108.661 U6_U2.15@188.925,107.17 188.925,105.308 v1(188.9,105.283) ; C5_U2.2@227.406,109.474 227.406,109.245 228.778,107.874 v1@228.778,103.734
  Top Layer w1.27: 144.983,93.243 145.263,93.243 147.828,95.809 ; R21_U2.1@145.212,89.002 145.212,89.941 148.438,93.167 148.438,94.64 ; 146.761,93.497 148.438,95.174 ; 149.123,92.329 149.225,92.431 149.225,95.428 ; 149.225,97.257 149.225,96.266 ; 149.555,98.933 148.438,97.815 ; 150.089,96.291 149.225,95.428 ; 152.095,96.825 153.594,96.825 153.619,96.85 ; 153.213,97.003 155.829,97.003 ; 157.277,99.06 157.937,99.72 159.766,99.72 ; T1_U2.4@163.307,108.232 165.123,108.232 165.887,107.467 ; 165.557,98.044 165.557,98.654 168.072,101.168 ; 187.681,109.906 176.428,109.906 175.539,110.795 166.294,110.795 165.887,110.388 165.887,107.467 ; 188.112,109.474 188.112,111.404 188.824,112.116 R31_U2.2@192.634,112.116 194.361,112.116 C41_U2.2@194.97,112.725 C41_U2.2@194.92,112.776 ; C42_U2.2@194.945,110.439 C41_U2.2@194.945,112.522 ; v3(202.794,116.586) U16_U2.4@204.013,116.586 ; 206.781,105.029 208.509,105.029 208.509,103.937 v5@208.153,103.581 ; C6_U2.2@206.959,109.576 C6_U2.2@206.985,109.601 ; v5@208.509,103.581 v5@208.153,103.581 ; 208.509,105.156 U9_U2.15@208.509,107.17 ; 213.411,112.624 213.309,112.725 ; 213.462,114.427 R58_U2.1@214.859,114.427 ; P4_U2.2@213.718,129.952 213.718,129.324 213.147,128.753 213.147,128.301 212.893,128.047 212.893,124.698 213.309,124.282 213.309,112.725 ; C66_U2.2@213.893,111.785 208.153,111.785 ; C67_U2.2@214.224,110.134 213.309,111.049 213.309,112.725 ; C67_U2.2@214.401,109.728 C66_U2.2@214.401,111.862 ; v1@219.558,111.836 219.583,111.862 219.583,112.674 219.786,112.674 Q6_U2.2@219.812,112.7 ; R8_U2.1@226.187,113.462 226.187,109.957 C5_U2.2@226.365,109.779 ; 226.339,111.709 233.197,111.709 234.086,110.82 C49_U2.2@234.086,110.16 ; R63_U2.2@231.724,111.887 231.902,112.065 C50_U2.2@231.902,113.868 ; 147.828,95.809 148.438,96.418 ; 147.828,95.809 147.828,98.501 148.438,99.111 ; 148.438,94.64 149.225,95.428 ; 148.438,94.64 148.438,95.174 ; 148.438,95.174 148.438,95.479 ; 148.438,95.479 148.438,96.418 ; 148.438,95.479 149.225,96.266 ; 148.438,96.418 148.438,97.815 ; 148.438,97.815 148.438,99.111 ; 148.438,99.111 149.987,100.66 158.826,100.66 159.766,99.72 ; 149.225,95.428 149.225,96.266 ; 159.766,99.72 165.557,99.72 165.887,100.051 165.887,101.092 ; 165.887,101.092 165.887,103.022 ; 165.887,101.092 165.964,101.168 168.072,101.168 ; 165.887,103.022 166.573,102.337 ; 165.887,103.022 165.887,107.467 ; 166.573,102.337 167.488,101.422 170.104,101.422 R45_U2.1@170.256,101.27 ; 166.573,102.337 172.593,102.337 172.669,102.413 172.669,101.498 172.441,101.27 R45_U2.1@170.256,101.27 ; 168.072,101.168 169.291,101.168 ; 169.291,101.168 R45_U2.1@170.358,101.168 R45_U2.1@170.256,101.27 ; 169.291,101.168 169.393,101.27 R45_U2.1@170.256,101.27 ; C6_U2.2@206.985,109.601 206.985,109.525 205.664,108.204 v3(205.664,106.655) 205.664,106.07 v5@208.153,103.581 ; C6_U2.2@206.985,109.601 C6_U2.2@206.985,110.033 206.985,111.658 207.112,111.785 208.153,111.785 ; C6_U2.2@206.985,109.601 207.518,110.134 207.772,110.134 207.772,111.404 208.153,111.785
  Top Layer w2.032: C10_U2.1@227.838,124.866 227.838,132.385 v3(227.889,132.436)
  Bottom Layer w1.27: 187.249,103.378 v1@188.9,105.029 ; v1(188.9,105.283) v1@188.9,105.029 ; P4_U2.23@201.336,128.047 201.336,128.372 202.288,129.324 P4_U2.8@202.288,129.952 ; v3@202.743,116.586 v3(202.794,116.586) ; v5@208.636,103.581 v5(208.712,103.581) v1@228.498,103.581 ; v3@215.087,111.709 v1@219.354,111.709 ; v1@188.9,105.029 188.9,104.165 188.874,104.191 188.874,102.997 191.059,105.181 ; v1@188.9,105.029 189.052,105.181 191.059,105.181 ; 191.059,105.181 199.161,105.181 ; 199.161,105.181 200.939,105.181 202.438,106.68 202.463,106.655 203.302,106.655 ; 199.161,105.181 201.727,107.747 203.302,107.747 ; v3(202.794,116.586) 203.098,116.586 205.664,114.021 v3(205.664,106.655) 204.521,106.655 ; v3(202.794,116.586) 202.794,115.138 203.302,114.63 ; 203.302,106.655 203.302,107.747 ; 203.302,106.655 204.521,106.655 ; 203.302,107.747 203.302,114.63 ; 203.302,114.63 204.445,113.487 204.445,106.731 204.521,106.655
  Bottom Layer w2.032: P4_U2.8@202.288,129.952 202.288,132.006 202.87,132.588 214.401,132.588 ; P4_U2.2@213.718,129.952 213.766,130 213.766,131.953 214.401,132.588 ; P2_U2.2@238.455,129.921 238.455,128.397 236.677,126.619 232.131,126.619 230.2,128.549 230.2,130.073 227.686,132.588 214.401,132.588
  other v1: 228.752,103.734 219.558,111.684
  other v3: 185.928,101.625 185.953,102.972 214.96,111.862
NetC13_U1_1: C13_U1.1 D2_U1.2 L1_U1.2 U3_U1.8
NetC13_U1_2: C13_U1.2 U3_U1.1 | length 3
  Top Layer w0.762: 9.347,121.234 10.338,121.234 11.024,120.548 C13_U1.2@11.024,119.482
NetC13_U2_1: C13_U2.1 D2_U2.2 L1_U2.2 U3_U2.8 | length 3.2
  Top Layer w0.762: 241.579,120.675 242.443,119.812 242.443,119.126 242.748,118.821 242.849,118.923 243.535,118.923
NetC13_U2_2: C13_U2.2 U3_U2.1 | length 3
  Top Layer w0.762: U3_U2.1@237.287,118.542 237.693,118.542 237.82,118.669 237.82,119.355 238.684,120.218 239.192,120.218
NetC14_U1_1: C14_U1.1 R13_U1.1 R14_U1.2 U4_U1.5 | length 9.1
  Top Layer w0.762: U4_U1.5@106.655,121.615 108.712,121.615 C14_U1.1@108.991,121.895 R14_U1.2@108.991,124.079 108.991,126.746 108.229,127.508 R13_U1.1@107.493,127.508
NetC14_U2_1: C14_U2.1 R13_U2.1 R14_U2.2 U4_U2.5 | length 7.1
  Top Layer w0.381: U4_U2.5@166.294,118.821 168.707,118.821 ; C14_U2.1@168.707,117.856 168.707,118.821 ; 168.732,118.796 168.707,118.821 ; R14_U2.2@171.247,120.066 R13_U2.1@168.859,120.066 168.707,119.913 168.707,118.821
NetC23_U1_2: C23_U1.2 R19_U1.1 R22_U1.2 U3_U1.5 | length 14.2
  Top Layer w1.016: R22_U1.2@1.93,109.753 1.93,107.645 2.261,107.315 v1(4.826,107.315) C23_U1.2@5.893,107.315 ; v1(4.801,113.817) 4.801,114.224 4.775,114.249 4.851,114.325 5.029,114.325 5.232,114.529 U3_U1.5@5.232,115.037
  Bottom Layer w1.016: v1(4.801,113.817) 4.826,113.792 v1(4.826,107.315)
NetC23_U2_2: C23_U2.2 R19_U2.1 R22_U2.2 U3_U2.5 | length 16.1
  Top Layer w0.762: U3_U2.5@243.434,114.732 243.027,114.732 241.656,113.36 R22_U2.2@241.656,112.573 241.656,112.141 242.9,110.896 249.377,110.896 R19_U2.1@250.825,112.344
  Top Layer w1.27: R19_U2.1@250.825,112.344 C23_U2.2@250.825,114.63
NetC26_U1_2: C26_U1.2 U3_U1.4 | length 1.2
  Top Layer w1.27: C26_U1.2@3.683,121.59 4.648,121.59 4.826,121.412
NetC26_U2_2: C26_U2.2 U3_U2.4 | length 1.7
  Top Layer w0.762: C26_U2.2@237.312,112.751 237.312,114.478
NetC27_U1_2: C27_U1.2 C28_U1.2 U3_U1.6 | length 6.9
  Top Layer w0.762: U3_U1.6@6.502,115.037 6.502,113.868 6.909,113.462 7.798,113.462 8.026,113.233 8.026,112.319 8.382,111.963 C27_U1.2@8.788,111.963 8.788,109.83 C28_U1.2@8.763,109.804
NetC27_U2_2: C27_U2.2 C28_U2.2 U3_U2.6 | length 5.6
  Top Layer w0.762: U3_U2.6@243.434,116.002 244.856,116.002 245.923,117.069 C27_U2.2@246.431,117.069 C28_U2.2@248.564,117.069
NetC28_U1_1: C28_U1.1 R25_U1.2 | length 2.2
  Top Layer w0.762: R25_U1.2@4.242,109.753 4.293,109.804 C28_U1.1@6.375,109.804
NetC28_U2_1: C28_U2.1 R25_U2.2 | length 2.2
  Top Layer w1.27: R25_U2.2@248.463,112.522 248.564,112.624 C28_U2.1@248.564,114.681
NetC31_U1_1: C31_U1.1 R28_U1.2 R29_U1.1 | length 8.8
  Top Layer w0.381: C31_U1.1@98.171,122.174 98.171,119.075 99.136,118.11 101.702,118.11 102.768,119.177 R29_U1.1@102.768,119.456
NetC31_U2_1: C31_U2.1 R28_U2.2 R29_U2.1 | length 8.9
  Top Layer w0.381: C31_U2.1@157.048,116.738 157.048,115.849 157.556,115.341 161.188,115.341 161.519,115.672 161.519,116.688 R28_U2.2@161.544,116.713
  Top Layer w0.762: R28_U2.2@161.544,116.713 R29_U2.1@163.678,116.713
NetC32_U1_1: C32_U1.1 D7_U1.2 U6_U1.7 | length 17.2
  Top Layer w0.508: U6_U1.7@34.392,97.942 34.417,97.917 34.417,95.834 35.281,94.971 35.281,90.907 C32_U1.1@34.773,90.399
  Top Layer w1.016: U6_U1.7@34.392,97.942 34.392,99.898 34.544,100.051 36.398,100.051 37.109,99.339 37.109,98.044 37.922,97.231 D7_U1.2@39.573,97.231
NetC32_U2_1: C32_U2.1 D7_U2.2 U6_U2.7 | length 17.7
  Top Layer w0.762: C32_U2.1@194.97,88.113 195.275,88.417 195.275,91.11 195.275,93.853 U6_U2.7@195.275,96.52 U6_U2.7@195.275,96.723 ; D7_U2.2@199.492,95.707 197.841,95.707 197.612,95.936 197.612,97.714 196.901,98.425 195.885,98.425 195.351,97.892 ; U6_U2.7@195.275,96.723 195.351,96.799 195.351,97.892 ; U6_U2.7@195.275,96.723 195.275,97.815 195.351,97.892
NetC33_U1_1: C33_U1.1 R28_U1.1 U4_U1.3 | length 12.6
  Top Layer w0.381: R28_U1.1@100.559,119.558 100.559,119.888 99.162,121.285 99.162,122.453 99.593,122.885 U4_U1.3@100.508,122.885 102.21,122.885 102.87,123.546 102.87,126.136 101.803,127.203 C33_U1.1@100.889,127.203
NetC33_U2_1: C33_U2.1 R28_U2.1 U4_U2.3 | length 11.1
  Top Layer w0.381: R28_U2.1@159.156,116.713 158.648,117.221 158.648,119.736 159.004,120.091 U4_U2.3@160.147,120.091 161.442,120.091 162.154,120.802 C33_U2.1@162.154,124.689
NetC36_U1_1: C36_U1.1 C37_U1.1 P3_U1.1 T1_U1.1 | length 2.4
  Top Layer w0.762: C37_U1.1@90.195,94.132 90.195,91.999 C36_U1.1@90.399,91.796
NetC36_U1_2: C36_U1.2 C37_U1.2 P3_U1.2 T1_U1.3 | length 22.7
  Top Layer w1.27: C37_U1.2@87.808,94.132 87.808,86.665 89.052,85.42 P3_U1.2@93.294,85.42 93.548,85.674 95.555,85.674 96.345,86.464 T1_U1.3@96.345,92.227
NetC36_U2_1: C36_U2.1 C37_U2.1 P3_U2.1 T1_U2.1 | length 14.4
  Top Layer w1.27: T1_U2.1@170.307,105.232 C36_U2.1@173.152,105.232 179.299,105.232 182.22,108.153 P3_U2.1@183.515,108.153
NetC36_U2_2: C36_U2.2 C37_U2.2 P3_U2.2 T1_U2.3 | length 14.3
  Top Layer w1.27: T1_U2.3@170.282,108.232 177.924,108.232 v3(178.638,107.518)
  Bottom Layer w1.27: v3(178.638,107.518) 180.543,105.613 P3_U2.2@183.515,105.613
NetC45_U1_1: C45_U1.1 R43_U1.2 R44_U1.1 | length 9.3
  Top Layer w0.508: R44_U1.1@86.893,119.304 89.23,119.304 R43_U1.2@89.306,119.38
  Top Layer w0.762: C45_U1.1@93.777,119.405 94.336,119.405 v1(94.361,119.431)
  Bottom Layer w0.762: v1(88.113,119.38) 88.163,119.431 v1(94.361,119.431)
NetC45_U2_1: C45_U2.1 R43_U2.2 R44_U2.1 | length 5.1
  Top Layer w0.381: R43_U2.2@174.498,119.202 174.498,119.177 176.657,117.018 R44_U2.1@176.708,117.018 176.733,116.992 C45_U2.1@178.689,116.992
NetC46_U1_1: C46_U1.1 R43_U1.1 U8_U1.3 | length 10.8
  Top Layer w0.508: R43_U1.1@91.694,119.38 91.694,123.419 92.481,124.206 ; C46_U1.1@94.056,127.203 93.447,127.203 92.481,126.238 92.481,124.206 ; U8_U1.3@94.107,124.206 92.481,124.206
NetC46_U2_1: C46_U2.1 R43_U2.1 U8_U2.3 | length 4.9
  Top Layer w0.381: R43_U2.1@174.498,121.59 176.733,121.59 C46_U2.1@176.759,121.564 177.952,120.371 U8_U2.3@178.918,120.371
NetC47_U1_2: C47_U1.2 D12_U1.2 U9_U1.7 | length 16.3
  Top Layer w0.508: C47_U1.2@55.956,90.678 C47_U1.2@56.032,90.602
  Top Layer w1.016: C47_U1.2@55.956,90.678 55.956,96.037 55.397,96.596 U9_U1.7@55.397,97.942 55.397,99.314 56.007,99.924 57.404,99.924 57.963,99.365 57.963,97.917 58.598,97.282 D12_U1.2@60.477,97.282
NetC47_U2_2: C47_U2.2 D12_U2.2 U9_U2.7 | length 17.4
  Top Layer w0.508: U9_U2.7@214.859,96.52 214.859,95.326 215.824,94.361 C47_U2.2@215.824,88.24
  Top Layer w0.762: U9_U2.7@214.859,96.52 214.859,97.942 215.265,98.349 216.891,98.349 217.322,97.917 217.322,96.418 217.907,95.834 D12_U2.2@220.116,95.834
NetC48_U1_1: C48_U1.1 R56_U1.2 R57_U1.1 | length 5.4
  Top Layer w0.762: C48_U1.1@83.083,121.691 83.083,122.149 84.049,123.114 84.049,126.035 84.023,126.035 R56_U1.2@83.566,126.492
NetC48_U2_1: C48_U2.1 R56_U2.2 R57_U2.1 | length 4.8
  Top Layer w0.381: C48_U2.1@187.554,119.05 C48_U2.1@187.325,119.278 187.35,119.304 R57_U2.1@189.636,119.304 ; R56_U2.2@189.586,116.916 R57_U2.1@189.586,119.101
NetC53_U1_1: C53_U1.1 R56_U1.1 U8_U1.5 | length 4.9
  Top Layer w0.508: C53_U1.1@85.903,128.651 85.903,126.543 R56_U1.1@85.954,126.492
  Top Layer w0.762: R56_U1.1@85.954,126.492 85.954,125.908 86.385,125.476 U8_U1.5@87.96,125.476
NetC53_U2_1: C53_U2.1 R56_U2.1 U8_U2.5 | length 4.2
  Top Layer w0.381: U8_U2.5@185.064,119.101 185.344,118.821 C53_U2.1@185.344,116.992 R56_U2.1@187.325,116.992
NetC54_U1_2: C54_U1.2 D17_U1.2 U11_U1.7 | length 16.3
  Top Layer w0.762: C54_U1.2@76.606,90.424 76.606,95.656 75.108,97.155 U11_U1.7@75.108,97.968 75.108,99.365 75.489,99.746 76.987,99.746 77.394,99.339 77.394,98.222 78.156,97.46 D17_U1.2@80.061,97.46
NetC54_U2_2: C54_U2.2 D17_U2.2 U11_U2.7 | length 17.4
  Top Layer w0.508: U11_U2.7@235.128,96.495 235.128,95.733 237.134,93.726 C54_U2.2@237.134,88.214
  Top Layer w0.762: U11_U2.7@235.128,96.495 235.128,97.968 235.61,98.45 237.058,98.45 237.566,97.942 237.566,96.926 238.557,95.936 D17_U2.2@240.106,95.936
NetC61_U1_1: C61_U1.1 R69_U1.2 R70_U1.1 | length 4.5
  Top Layer w1.016: C61_U1.1@101.371,110.693 101.397,110.668 R70_U1.1@101.397,108.433 R69_U1.2@103.581,108.433
NetC61_U2_1: C61_U2.1 R69_U2.2 R70_U2.1 | length 4.4
  Top Layer w0.508: C61_U2.1@247.955,102.159 248.031,102.235 R69_U2.2@250.292,102.235 250.292,100.279 R70_U2.1@250.241,100.228
NetC64_U1_1: C64_U1.1 R69_U1.1 U13_U1.3 | length 7.6
  Top Layer w0.508: U13_U1.3@100.051,115.265 101.27,115.265 101.803,114.732 101.803,113.157 102.184,112.776 103.403,112.776 C64_U1.1@103.53,112.903
  Top Layer w1.016: C64_U1.1@103.53,112.903 103.581,112.852 R69_U1.1@103.581,110.82
NetC64_U2_1: C64_U2.1 R69_U2.1 U13_U2.3 | length 9.6
  Top Layer w0.762: R69_U2.1@250.292,104.623 250.292,104.47 252.4,102.362 253.898,102.362 254.025,102.489 U13_U2.3@254.025,103.962 254.025,105.181 255.067,106.223 C64_U2.1@255.067,106.807
NetC69_U1_2: C69_U1.2 R78_U1.1 R79_U1.2 U14_U1.2 V1_U1.3 | length 20
  Top Layer w0.381: U14_U1.2@16.51,88.163 16.51,85.801 C69_U1.2@16.459,85.75 17.45,84.76 V1_U1.3@17.45,81.966 ; V1_U1.3@17.551,82.067 20.472,79.146 20.472,75.692 19.05,74.27 R78_U1.1@19.05,72.746
  Top Layer w0.762: R79_U1.2@16.815,72.822 18.974,72.822 R78_U1.1@19.05,72.746
NetC69_U2_2: C69_U2.2 R78_U2.1 R79_U2.2 U14_U2.2 V1_U2.3 | length 20
  Top Layer w0.508: U14_U2.2@253.06,78.08 253.06,79.985 253.517,80.442 256.174,80.442 256.743,79.872 256.743,76.733 256.388,76.378 V1_U2.3@256.388,74.016
  Top Layer w0.762: R79_U2.2@249.758,72.771 251.866,72.771 C69_U2.2@251.917,72.72 251.917,75.133 R78_U2.1@251.993,75.209 251.993,75.362 253.06,76.429 U14_U2.2@253.06,78.08
NetD1_U1_2: D1_U1.2 R8_U1.2 | length 2.3
  Top Layer w1.016: D1_U1.2@17.678,111.811 17.78,111.709 R8_U1.2@19.939,111.709
NetD1_U2_2: D1_U2.2 R8_U2.2 | length 2.2
  Top Layer w1.27: D1_U2.2@226.06,117.958 226.06,115.976 R8_U2.2@226.187,115.849
NetD3_U1_2: D3_U1.2 R16_U1.1 | length 2.4
  Top Layer w1.016: R16_U1.1@1.422,102.718 3.531,102.718 D3_U1.2@3.708,102.54
NetD3_U2_2: D3_U2.2 R16_U2.1 | length 2.4
  Top Layer w1.27: D3_U2.2@258.547,119.431 258.547,117.043 R16_U2.1@258.572,117.018
NetD5_U1_1: D5_U1.1 Q2_U1.1 R27_U1.2 R30_U1.1 | length 24.1
  Top Layer w0.508: Q2_U1.1@25.12,74 Q2_U1.1@25.12,74.98 ; R27_U1.2@35.56,82.906 35.712,82.753 R30_U1.1@35.712,80.67 35.738,80.645 R30_U1.1@36,80.383 ; 36.805,78.613 36.881,78.689
  Top Layer w0.762: R30_U1.1@35.738,80.645 36.881,80.645 ; v1(36.906,77.114) 36.881,77.14 36.881,78.689 36.881,80.645 ; D5_U1.1@38.456,80.645 36.881,80.645
  Bottom Layer w0.762: Q2_U1.1@25.12,74 25.12,75.463 26.822,77.165 v1@36.957,77.165
NetD5_U1_2: D5_U1.2 R23_U1.2 | length 3.4
  Top Layer w0.508: D5_U1.2@38.456,84.945 39.218,85.707 R23_U1.2@39.218,88.011
NetD5_U2_1: D5_U2.1 Q2_U2.1 R27_U2.2 R30_U2.1 | length 19.6
  Top Layer w0.508: R27_U2.2@195.453,80.086 195.453,78.08 R30_U2.1@195.605,77.927 R30_U2.1@196.041,77.927 ; 196.113,78.232 196.041,78.16 R30_U2.1@196.041,77.927 ; D5_U2.1@198.298,78.181 198.044,77.927 R30_U2.1@196.041,77.927
  Top Layer w0.762: R30_U2.1@195.605,77.927 195.707,77.826 v1(195.707,76.479)
  Bottom Layer w0.762: Q2_U2.1@185.141,72.898 185.877,73.635 185.877,74.905 187.452,76.479 v1(195.707,76.479)
NetD5_U2_2: D5_U2.2 R23_U2.2 | length 3.5
  Top Layer w0.508: D5_U2.2@198.298,82.481 199.009,83.192 R23_U2.2@199.009,85.725
NetD6_U1_2: D6_U1.2 D7_U1.1 | length 2.1
  Top Layer w1.016: D7_U1.1@39.268,101.879 D6_U1.2@39.268,104.013
NetD6_U2_2: D6_U2.2 D7_U2.1 | length 2.2
  Top Layer w0.762: D7_U2.1@200.076,100.533 D6_U2.2@200.076,102.692
NetD8_U1_2: D8_U1.2 R34_U1.1 | length 3.9
  Top Layer w1.016: R34_U1.1@93.751,62.179 93.751,63.424 95.326,64.999 D8_U1.2@95.326,65.43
